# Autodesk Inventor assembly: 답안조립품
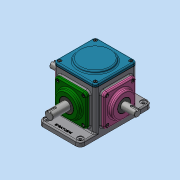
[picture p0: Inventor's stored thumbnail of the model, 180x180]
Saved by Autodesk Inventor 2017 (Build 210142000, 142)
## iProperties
Part Number: 답안조립품
Material: 일반
Document SubType Name: Assembly
Designer: MRC
Author: MRC
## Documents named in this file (16)
- C:\Users\MRC\Desktop\620307V1013\답안조립품.iam
- C:\Users\MRC\Desktop\620307V1013\본체.ipt
- C:\Users\MRC\Desktop\620307V1013\개스킷.ipt
- C:\Users\MRC\Desktop\620307V1013\메인베벨기어.ipt
- C:\Users\MRC\Desktop\620307V1013\메인축.ipt
- C:\Users\MRC\Desktop\620307V1013\메인커버.ipt
- C:\Users\MRC\Desktop\620307V1013\베어링 6203.ipt
- C:\Users\MRC\Desktop\620307V1013\베어링 6204.ipt
- C:\Users\MRC\Desktop\620307V1013\볼트 M4.ipt
- C:\Users\MRC\Desktop\620307V1013\상부커버.ipt
- C:\Users\MRC\Desktop\620307V1013\서브베벨기어.ipt
- C:\Users\MRC\Desktop\620307V1013\서브축.ipt
- C:\Users\MRC\Desktop\620307V1013\서브커버.ipt
- C:\Users\MRC\Desktop\620307V1013\오일 실 17 32 8.ipt
- C:\Users\MRC\Desktop\620307V1013\오일 실 20 35 8.ipt
- C:\Users\MRC\Desktop\620307V1013\키 4x4.ipt
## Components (1 placed, 1 different names)
1. 개스킷:1
